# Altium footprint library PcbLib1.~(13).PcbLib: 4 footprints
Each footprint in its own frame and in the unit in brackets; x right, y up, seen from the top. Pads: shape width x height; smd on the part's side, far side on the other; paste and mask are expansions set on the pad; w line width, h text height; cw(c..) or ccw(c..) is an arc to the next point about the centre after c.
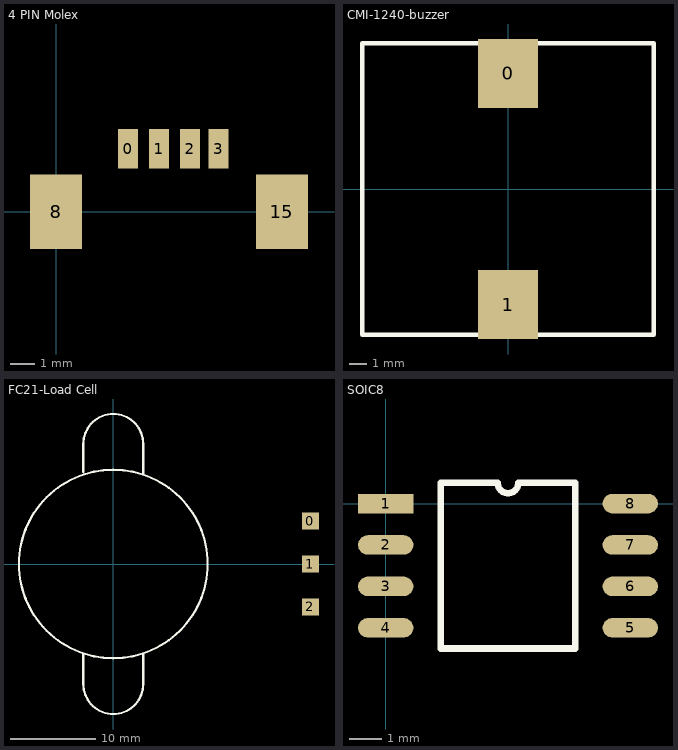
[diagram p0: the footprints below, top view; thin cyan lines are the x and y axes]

## 4 PIN Molex [mm]
pads (6):
  rect 0.8x1.6 smd: 0(2.9,2.55) 1(4.15,2.55) 2(5.4,2.55) 3(6.55,2.55)
  rect 2.1x3 smd: 8(0,0) 15(9.1,0)

## CMI-1240-buzzer [mm]
pads (2):
  rect 3.5x4 smd: 0(0,6.7) 1(0,-6.7)
Top Overlay:
  lines w0.254: -8.45,-8.45 8.45,-8.45 8.45,8.45 -8.45,8.45 -8.45,-8.45

## FC21-Load Cell [mm]
pads (3):
  rect 2x2 smd: 0(23,5) 1(23,0) 2(23,-5)
Top Overlay:
  circle w0.254: c0,0 r11
  lines w0.254: -3.5,-10.47 -3.5,-14 ccw(c0,-14) 3.5,-14 3.5,-10.485 ; -3.5,10.724 -3.5,14 cw(c0,14) 3.5,14 3.5,10.485

## SOIC8 [mm]
pads (8):
  rect 1.7x0.6 smd: 1(0,0)
  oval 1.7x0.6 smd: 2(0,-1.27) 3(0,-2.54) 4(0,-3.81) 5(7.5,-3.81) 6(7.5,-2.54) 7(7.5,-1.27) 8(7.5,0)
Top Overlay:
  lines w0.2: 1.685,-4.445 1.685,0.635 3.433,0.635 ccw(c3.75,0.635) 4.068,0.635 5.815,0.635 5.815,-4.445 1.685,-4.445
